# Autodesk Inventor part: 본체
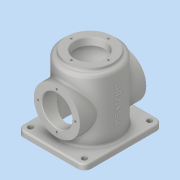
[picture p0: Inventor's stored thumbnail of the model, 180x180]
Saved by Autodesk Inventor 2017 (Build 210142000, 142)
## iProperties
Part Number: 본체
Material: 알루미늄 6061
Document SubType Name: Modeling
Designer: MRC
Density: 2.7 g/cm^3
Appearance: 알루미늄 - 평지
Mass: 1235.53 g
Surface Area: 1067.6 cm^2
Volume: 457.603 cm^3
Author: MRC
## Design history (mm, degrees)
sketch "스케치1"
  geometry: C1 r 50 at (0, 0); 1 further point
  constraints: 1 centre point, 1 coincident
  dimensions: "d0" = 100 diameter of C1
extrude "돌출1" new body sketch "스케치1" stored distance "d1" = 120; taper "d2" = 0 deg
sketch "스케치2"
  geometry: L1 (-60, 70)-(60, 70); L2 (60, 70)-(60, -70); L3 (60, -70)-(-60, -70); L4 (-60, -70)-(-60, 70); L5 (-60, 70)-(60, -70); L6 (60, 70)-(-60, -70); C1 r 50 at (0, 0) reference
  constraints: 12 end point, 2 midpoint, 2 parallel, 1 horizontal, 1 perpendicular
  dimensions: "d3" = 120 distance of L2.end L3.end; "d4" = 140 distance of L1.end L2.end
extrude "돌출2" join sketch "스케치2" distance "d5" = 10; taper "d6" = 0 deg
sketch "스케치3"
  geometry: C1 r 50 at (0, 0) reference; C2 r 41 at (0, 0)
  constraints: 1 centre point, 1 coincident
  dimensions: "d7" = 82 diameter of C2
extrude "돌출3" join sketch "스케치3" distance "d8" = 5; taper "d9" = 0 deg
sketch "스케치5"
  geometry: C1 r 41 at (0, 0) reference; C2 r 27 at (0, 0)
  constraints: 1 centre point, 1 coincident
  dimensions: "d13" = 54 diameter of C2
extrude "돌출5" cut sketch "스케치5" distance "d14" = 13; taper "d15" = 0 deg
sketch "스케치6"
  geometry: C1 r 41 at (0, 0); 1 further point
  constraints: 1 centre point, 1 coincident
  dimensions: "d16" = 82 diameter of C1
extrude "돌출6" join sketch "스케치6" stored distance "d17" = 118; taper "d18" = 0 deg
sketch "스케치7"
  geometry: C1 r 41 at (0, 0) reference; C2 r 27 at (0, 0)
  constraints: 1 centre point, 1 coincident
  dimensions: "d19" = 54 diameter of C2
extrude "돌출7" cut sketch "스케치7" stored distance "d20" = 118; taper "d21" = 0 deg
sketch "스케치8"
  geometry: C1 r 27 at (0, 0) reference; 1 further point
  constraints: 1 vertical alignment
  dimensions: "d22" = 33 distance of C1.centre point (0, 33)
hole "구멍1" sketch "스케치8" at (0, 33) diameter "d23" = 3.242; stored, may be unused: countersink angle "d27" = 90 deg, drill point angle "d29" = 118 deg; dims "d24" = 8, "d25" = 4, "d26" = 2, "d28" = 10
sketch "스케치9"
  geometry: C1 r 27 at (0, 0) reference; 1 further point
  constraints: 1 vertical alignment
  dimensions: "d33" = 33 distance of C1.centre point (0, 33)
hole "구멍2" sketch "스케치9" at (0, 33) diameter "d34" = 3.242; stored, may be unused: countersink angle "d38" = 90 deg, drill point angle "d40" = 118 deg; dims "d35" = 8, "d36" = 4, "d37" = 2, "d39" = 10
fillet "모깎기1" dims "d44" = 12
sketch "스케치10"
  geometry: C1 r 4.5 at (-48, 58); A1 r 12 centre (-48, 58) between (-48, 70) and (-60, 58) reference
  constraints: 1 centre point, 1 coincident
  dimensions: "d45" = 9 diameter of C1
extrude "돌출8" cut sketch "스케치10" stored distance "d46" = 118; taper "d47" = 0 deg
fillet "모깎기2" dims "d48" = 3
chamfer "모따기1" distance "d49" = 1; stored, may be unused: second distance "d50" = 2, angle "d51" = 45 deg
chamfer "모따기2" distance "d52" = 1; stored, may be unused: second distance "d53" = 2, angle "d54" = 45 deg
fillet "모깎기3" dims "d55" = 6
fillet "모깎기4" dims "d56" = 3
fillet "모깎기5" dims "d57" = 3
fillet "모깎기6" dims "d58" = 3
sketch "스케치11"
  geometry: C1 r 42 at (0, 0); 1 further point
  constraints: 1 centre point, 1 coincident
  dimensions: "d59" = 84 diameter of C1
extrude "돌출9" cut sketch "스케치11" distance "d60" = 112; taper "d61" = 0 deg
fillet "모깎기7" dims "d62" = 3
node "작업 평면1"
sketch "스케치12"
  geometry: L1 (-60, 58)-(-60, -58) reference; 2 further points
  constraints: 1 horizontal alignment, 1 other
  dimensions: "d64" = 66 distance from line of L1 point (6, 0)
feature "엠보싱1" sketch "스케치12" dims "d1" = 120, "d65" = 0.5, "d66" = 0
node "솔리드1"
pattern_circular "원형 패턴1" dims angle "d31" = 360 deg
mirror "미러1"
pattern_circular "원형 패턴2" dims angle "d42" = 360 deg
mirror "미러2"
mirror "미러3"
other parameters: "d63" = 80.5
